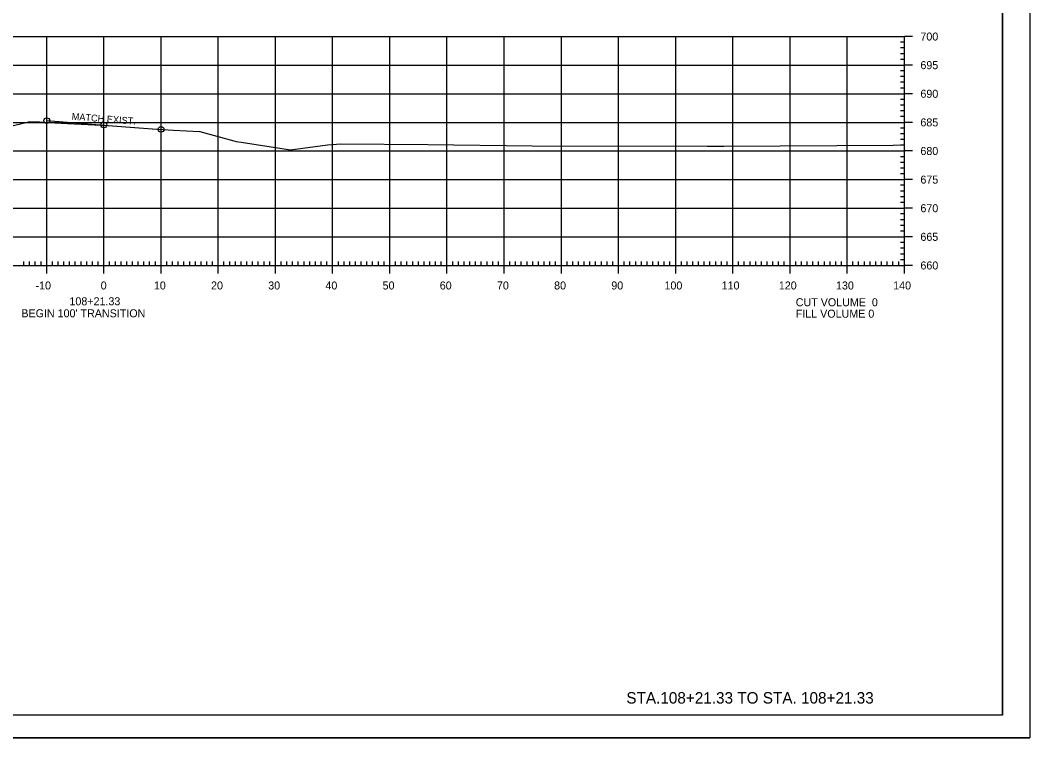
# Model space of a CAD drawing. Extents: x 1360146 to 1361431, y 631444 to 632352.
# Drawn here: x 1360303.1 to 1360479.7, y 631444.2 to 631569.6 of the extents above; entities that cross this region are included whole.
import ezdxf

# ---------------------------------------------------------------- set-up
doc = ezdxf.new("R2010")
doc.units = 0
for name, color, linetype in [('R_Axis', 7, 'Continuous'), ('R_Axis Annot', 7, 'Continuous'), ('R_Border', 7, 'Continuous'), ('R_Draft', 7, 'Continuous'), ('R_Exist Surface', 7, 'Continuous'), ('R_Fin Surface', 7, 'Continuous'), ('R_Fin Surface Annot', 7, 'Continuous'), ('R_Grid', 7, 'Continuous'), ('R_No Plot', 7, 'Continuous')]:
    doc.layers.add(name, color=color, linetype=linetype)

msp = doc.modelspace()

# ---------------------------------------------------------------- linework, layer by layer
at = {"layer": 'R_Axis'}
for p, q in [((1360457.77, 631526.7), (1360457.77, 631566.7)), ((1360459.17, 631566.7), (1360457.77, 631566.7)), ((1360457.77, 631565.7), (1360457.07, 631565.7)), ((1360457.77, 631564.7), (1360457.07, 631564.7)), ((1360457.77, 631563.7), (1360457.07, 631563.7)), ((1360457.77, 631562.7), (1360457.07, 631562.7)), ((1360459.17, 631561.7), (1360457.77, 631561.7)), ((1360457.77, 631560.7), (1360457.07, 631560.7)), ((1360457.77, 631559.7), (1360457.07, 631559.7)), ((1360457.77, 631558.7), (1360457.07, 631558.7)), ((1360457.77, 631557.7), (1360457.07, 631557.7)), ((1360459.17, 631556.7), (1360457.77, 631556.7)), ((1360457.77, 631555.7), (1360457.07, 631555.7)), ((1360457.77, 631554.7), (1360457.07, 631554.7)), ((1360457.77, 631553.7), (1360457.07, 631553.7)), ((1360457.77, 631552.7), (1360457.07, 631552.7)), ((1360459.17, 631551.7), (1360457.77, 631551.7)), ((1360457.77, 631550.7), (1360457.07, 631550.7)), ((1360457.77, 631549.7), (1360457.07, 631549.7)), ((1360457.77, 631548.7), (1360457.07, 631548.7)), ((1360457.77, 631547.7), (1360457.07, 631547.7)), ((1360457.77, 631545.7), (1360457.07, 631545.7)), ((1360459.17, 631546.7), (1360457.77, 631546.7)), ((1360457.77, 631544.7), (1360457.07, 631544.7)), ((1360457.77, 631543.7), (1360457.07, 631543.7)), ((1360457.77, 631542.7), (1360457.07, 631542.7)), ((1360457.77, 631540.7), (1360457.07, 631540.7)), ((1360459.17, 631541.7), (1360457.77, 631541.7)), ((1360457.77, 631539.7), (1360457.07, 631539.7)), ((1360457.77, 631538.7), (1360457.07, 631538.7)), ((1360457.77, 631537.7), (1360457.07, 631537.7)), ((1360459.17, 631536.7), (1360457.77, 631536.7)), ((1360457.77, 631535.7), (1360457.07, 631535.7)), ((1360457.77, 631534.7), (1360457.07, 631534.7)), ((1360457.77, 631533.7), (1360457.07, 631533.7)), ((1360457.77, 631532.7), (1360457.07, 631532.7)), ((1360459.17, 631531.7), (1360457.77, 631531.7)), ((1360457.77, 631530.7), (1360457.07, 631530.7)), ((1360457.77, 631529.7), (1360457.07, 631529.7)), ((1360457.77, 631528.7), (1360457.07, 631528.7)), ((1360177.77, 631526.7), (1360457.77, 631526.7)), ((1360303.77, 631526.7), (1360303.77, 631527.4)), ((1360304.77, 631526.7), (1360304.77, 631527.4)), ((1360305.77, 631526.7), (1360305.77, 631527.4)), ((1360306.77, 631526.7), (1360306.77, 631527.4)), ((1360307.77, 631525.3), (1360307.77, 631526.7)), ((1360308.77, 631526.7), (1360308.77, 631527.4)), ((1360309.77, 631526.7), (1360309.77, 631527.4)), ((1360310.77, 631526.7), (1360310.77, 631527.4)), ((1360311.77, 631526.7), (1360311.77, 631527.4)), ((1360312.77, 631526.7), (1360312.77, 631527.4)), ((1360313.77, 631526.7), (1360313.77, 631527.4)), ((1360314.77, 631526.7), (1360314.77, 631527.4)), ((1360315.77, 631526.7), (1360315.77, 631527.4)), ((1360316.77, 631526.7), (1360316.77, 631527.4)), ((1360317.77, 631525.3), (1360317.77, 631526.7)), ((1360318.77, 631526.7), (1360318.77, 631527.4)), ((1360319.77, 631526.7), (1360319.77, 631527.4)), ((1360320.77, 631526.7), (1360320.77, 631527.4)), ((1360321.77, 631526.7), (1360321.77, 631527.4)), ((1360322.77, 631526.7), (1360322.77, 631527.4)), ((1360323.77, 631526.7), (1360323.77, 631527.4)), ((1360324.77, 631526.7), (1360324.77, 631527.4)), ((1360325.77, 631526.7), (1360325.77, 631527.4)), ((1360326.77, 631526.7), (1360326.77, 631527.4)), ((1360327.77, 631525.3), (1360327.77, 631526.7)), ((1360328.77, 631526.7), (1360328.77, 631527.4)), ((1360329.77, 631526.7), (1360329.77, 631527.4)), ((1360330.77, 631526.7), (1360330.77, 631527.4)), ((1360331.77, 631526.7), (1360331.77, 631527.4)), ((1360332.77, 631526.7), (1360332.77, 631527.4)), ((1360333.77, 631526.7), (1360333.77, 631527.4)), ((1360334.77, 631526.7), (1360334.77, 631527.4)), ((1360335.77, 631526.7), (1360335.77, 631527.4)), ((1360336.77, 631526.7), (1360336.77, 631527.4)), ((1360337.77, 631525.3), (1360337.77, 631526.7)), ((1360338.77, 631526.7), (1360338.77, 631527.4)), ((1360339.77, 631526.7), (1360339.77, 631527.4)), ((1360340.77, 631526.7), (1360340.77, 631527.4)), ((1360341.77, 631526.7), (1360341.77, 631527.4)), ((1360342.77, 631526.7), (1360342.77, 631527.4)), ((1360343.77, 631526.7), (1360343.77, 631527.4)), ((1360344.77, 631526.7), (1360344.77, 631527.4)), ((1360345.77, 631526.7), (1360345.77, 631527.4)), ((1360346.77, 631526.7), (1360346.77, 631527.4)), ((1360347.77, 631525.3), (1360347.77, 631526.7)), ((1360348.77, 631526.7), (1360348.77, 631527.4)), ((1360349.77, 631526.7), (1360349.77, 631527.4)), ((1360350.77, 631526.7), (1360350.77, 631527.4)), ((1360351.77, 631526.7), (1360351.77, 631527.4)), ((1360352.77, 631526.7), (1360352.77, 631527.4)), ((1360353.77, 631526.7), (1360353.77, 631527.4)), ((1360354.77, 631526.7), (1360354.77, 631527.4)), ((1360355.77, 631526.7), (1360355.77, 631527.4)), ((1360356.77, 631526.7), (1360356.77, 631527.4)), ((1360357.77, 631525.3), (1360357.77, 631526.7)), ((1360358.77, 631526.7), (1360358.77, 631527.4)), ((1360359.77, 631526.7), (1360359.77, 631527.4)), ((1360360.77, 631526.7), (1360360.77, 631527.4)), ((1360361.77, 631526.7), (1360361.77, 631527.4)), ((1360362.77, 631526.7), (1360362.77, 631527.4)), ((1360363.77, 631526.7), (1360363.77, 631527.4)), ((1360364.77, 631526.7), (1360364.77, 631527.4)), ((1360365.77, 631526.7), (1360365.77, 631527.4)), ((1360366.77, 631526.7), (1360366.77, 631527.4)), ((1360367.77, 631525.3), (1360367.77, 631526.7)), ((1360368.77, 631526.7), (1360368.77, 631527.4)), ((1360369.77, 631526.7), (1360369.77, 631527.4)), ((1360370.77, 631526.7), (1360370.77, 631527.4)), ((1360371.77, 631526.7), (1360371.77, 631527.4)), ((1360372.77, 631526.7), (1360372.77, 631527.4)), ((1360373.77, 631526.7), (1360373.77, 631527.4)), ((1360374.77, 631526.7), (1360374.77, 631527.4)), ((1360375.77, 631526.7), (1360375.77, 631527.4)), ((1360376.77, 631526.7), (1360376.77, 631527.4)), ((1360377.77, 631525.3), (1360377.77, 631526.7)), ((1360378.77, 631526.7), (1360378.77, 631527.4)), ((1360379.77, 631526.7), (1360379.77, 631527.4)), ((1360380.77, 631526.7), (1360380.77, 631527.4)), ((1360381.77, 631526.7), (1360381.77, 631527.4)), ((1360382.77, 631526.7), (1360382.77, 631527.4)), ((1360383.77, 631526.7), (1360383.77, 631527.4)), ((1360384.77, 631526.7), (1360384.77, 631527.4)), ((1360385.77, 631526.7), (1360385.77, 631527.4)), ((1360386.77, 631526.7), (1360386.77, 631527.4)), ((1360387.77, 631525.3), (1360387.77, 631526.7)), ((1360388.77, 631526.7), (1360388.77, 631527.4)), ((1360389.77, 631526.7), (1360389.77, 631527.4)), ((1360390.77, 631526.7), (1360390.77, 631527.4)), ((1360391.77, 631526.7), (1360391.77, 631527.4)), ((1360392.77, 631526.7), (1360392.77, 631527.4)), ((1360393.77, 631526.7), (1360393.77, 631527.4)), ((1360394.77, 631526.7), (1360394.77, 631527.4)), ((1360395.77, 631526.7), (1360395.77, 631527.4)), ((1360396.77, 631526.7), (1360396.77, 631527.4)), ((1360397.77, 631525.3), (1360397.77, 631526.7)), ((1360398.77, 631526.7), (1360398.77, 631527.4)), ((1360399.77, 631526.7), (1360399.77, 631527.4)), ((1360400.77, 631526.7), (1360400.77, 631527.4)), ((1360401.77, 631526.7), (1360401.77, 631527.4)), ((1360402.77, 631526.7), (1360402.77, 631527.4)), ((1360403.77, 631526.7), (1360403.77, 631527.4)), ((1360404.77, 631526.7), (1360404.77, 631527.4)), ((1360405.77, 631526.7), (1360405.77, 631527.4)), ((1360406.77, 631526.7), (1360406.77, 631527.4)), ((1360407.77, 631525.3), (1360407.77, 631526.7)), ((1360408.77, 631526.7), (1360408.77, 631527.4)), ((1360409.77, 631526.7), (1360409.77, 631527.4)), ((1360410.77, 631526.7), (1360410.77, 631527.4)), ((1360411.77, 631526.7), (1360411.77, 631527.4)), ((1360412.77, 631526.7), (1360412.77, 631527.4)), ((1360413.77, 631526.7), (1360413.77, 631527.4)), ((1360414.77, 631526.7), (1360414.77, 631527.4)), ((1360415.77, 631526.7), (1360415.77, 631527.4)), ((1360416.77, 631526.7), (1360416.77, 631527.4)), ((1360417.77, 631525.3), (1360417.77, 631526.7)), ((1360418.77, 631526.7), (1360418.77, 631527.4)), ((1360419.77, 631526.7), (1360419.77, 631527.4)), ((1360420.77, 631526.7), (1360420.77, 631527.4)), ((1360421.77, 631526.7), (1360421.77, 631527.4)), ((1360422.77, 631526.7), (1360422.77, 631527.4)), ((1360423.77, 631526.7), (1360423.77, 631527.4)), ((1360424.77, 631526.7), (1360424.77, 631527.4)), ((1360425.77, 631526.7), (1360425.77, 631527.4)), ((1360426.77, 631526.7), (1360426.77, 631527.4)), ((1360427.77, 631525.3), (1360427.77, 631526.7)), ((1360428.77, 631526.7), (1360428.77, 631527.4)), ((1360429.77, 631526.7), (1360429.77, 631527.4)), ((1360430.77, 631526.7), (1360430.77, 631527.4)), ((1360431.77, 631526.7), (1360431.77, 631527.4)), ((1360432.77, 631526.7), (1360432.77, 631527.4)), ((1360433.77, 631526.7), (1360433.77, 631527.4)), ((1360434.77, 631526.7), (1360434.77, 631527.4)), ((1360435.77, 631526.7), (1360435.77, 631527.4)), ((1360436.77, 631526.7), (1360436.77, 631527.4)), ((1360437.77, 631525.3), (1360437.77, 631526.7)), ((1360438.77, 631526.7), (1360438.77, 631527.4)), ((1360439.77, 631526.7), (1360439.77, 631527.4)), ((1360440.77, 631526.7), (1360440.77, 631527.4)), ((1360441.77, 631526.7), (1360441.77, 631527.4)), ((1360442.77, 631526.7), (1360442.77, 631527.4)), ((1360443.77, 631526.7), (1360443.77, 631527.4)), ((1360444.77, 631526.7), (1360444.77, 631527.4)), ((1360445.77, 631526.7), (1360445.77, 631527.4)), ((1360446.77, 631526.7), (1360446.77, 631527.4)), ((1360447.77, 631525.3), (1360447.77, 631526.7)), ((1360448.77, 631526.7), (1360448.77, 631527.4)), ((1360449.77, 631526.7), (1360449.77, 631527.4)), ((1360450.77, 631526.7), (1360450.77, 631527.4)), ((1360451.77, 631526.7), (1360451.77, 631527.4)), ((1360452.77, 631526.7), (1360452.77, 631527.4)), ((1360453.77, 631526.7), (1360453.77, 631527.4)), ((1360454.77, 631526.7), (1360454.77, 631527.4)), ((1360455.77, 631526.7), (1360455.77, 631527.4)), ((1360456.77, 631526.7), (1360456.77, 631527.4)), ((1360457.77, 631527.7), (1360457.07, 631527.7)), ((1360457.77, 631525.3), (1360457.77, 631526.7)), ((1360459.17, 631526.7), (1360457.77, 631526.7))]:
    msp.add_line(p, q, dxfattribs=at)
at = {"layer": 'R_Border'}
for q in [(1360474.95, 631653.6), (1360158.77, 631448.14)]:
    msp.add_line((1360474.95, 631448.14), q, dxfattribs=at)
at = {"layer": 'R_Exist Surface'}
msp.add_lwpolyline([(1360296.5, 631549.82), (1360304.82, 631551.87), (1360306.49, 631551.8), (1360308.06, 631551.7), (1360311.39, 631551.53), (1360318.51, 631551.14), (1360326.2, 631550.6), (1360329.94, 631550.32), (1360334.5, 631550.1), (1360334.54, 631550.09), (1360340.5, 631548.46), (1360340.89, 631548.37), (1360341.78, 631548.24), (1360350.38, 631546.92), (1360356.88, 631547.76), (1360359.2, 631547.98), (1360374.4, 631547.82), (1360392.65, 631547.58), (1360423.26, 631547.55), (1360425.06, 631547.55), (1360426.2, 631547.55), (1360455.81, 631547.73), (1360457.77, 631547.77)], dxfattribs=at)
at = {"layer": 'R_Fin Surface'}
msp.add_lwpolyline([(1360307.77, 631552), (1360307.77, 631552), (1360307.77, 631552), (1360317.76, 631551.24), (1360317.77, 631551.24), (1360327.76, 631550.48), (1360327.77, 631550.48), (1360327.77, 631550.48), (1360327.77, 631550.48)], dxfattribs=at)
at = {"layer": 'R_Grid'}
for p, q in [((1360177.77, 631566.7), (1360457.77, 631566.7)), ((1360307.77, 631526.7), (1360307.77, 631566.7)), ((1360317.77, 631526.7), (1360317.77, 631566.7)), ((1360327.77, 631526.7), (1360327.77, 631566.7)), ((1360337.77, 631526.7), (1360337.77, 631566.7)), ((1360347.77, 631526.7), (1360347.77, 631566.7)), ((1360357.77, 631526.7), (1360357.77, 631566.7)), ((1360367.77, 631526.7), (1360367.77, 631566.7)), ((1360377.77, 631526.7), (1360377.77, 631566.7)), ((1360387.77, 631526.7), (1360387.77, 631566.7)), ((1360397.77, 631526.7), (1360397.77, 631566.7)), ((1360407.77, 631526.7), (1360407.77, 631566.7)), ((1360417.77, 631526.7), (1360417.77, 631566.7)), ((1360427.77, 631526.7), (1360427.77, 631566.7)), ((1360437.77, 631526.7), (1360437.77, 631566.7)), ((1360447.77, 631526.7), (1360447.77, 631566.7)), ((1360457.77, 631526.7), (1360457.77, 631566.7)), ((1360177.77, 631561.7), (1360457.77, 631561.7)), ((1360177.77, 631556.7), (1360457.77, 631556.7)), ((1360177.77, 631551.7), (1360457.77, 631551.7)), ((1360177.77, 631546.7), (1360457.77, 631546.7)), ((1360177.77, 631541.7), (1360457.77, 631541.7)), ((1360177.77, 631536.7), (1360457.77, 631536.7)), ((1360177.77, 631531.7), (1360457.77, 631531.7)), ((1360177.77, 631526.7), (1360457.77, 631526.7))]:
    msp.add_line(p, q, dxfattribs=at)
at = {"layer": 'R_No Plot'}
msp.add_line((1360146.37, 631444.17), (1360479.7, 631444.17), dxfattribs=at)
for points in [[(1360146.36, 631657.5), (1360479.7, 631657.5), (1360479.7, 631444.16), (1360146.36, 631444.16)], [(1360392.69, 631653.6), (1360392.69, 631643.72), (1360428.42, 631643.72), (1360428.42, 631640.8), (1360451.62, 631640.8), (1360451.62, 631616.47), (1360474.95, 631616.47), (1360474.95, 631448.14), (1360158.77, 631448.14), (1360158.77, 631653.6)]]:
    msp.add_lwpolyline(points, close=True, dxfattribs=at)
for centre in [(1360307.77, 631552), (1360317.77, 631551.24), (1360327.77, 631550.48)]:
    msp.add_circle(centre, 0.5, dxfattribs=at)

# ---------------------------------------------------------------- texts
at = {"layer": 'R_Axis Annot'}
for s, p in [('700', (1360460.57, 631566)), ('695', (1360460.57, 631561)), ('690', (1360460.57, 631556)), ('685', (1360460.57, 631551)), ('680', (1360460.57, 631546)), ('675', (1360460.57, 631541)), ('670', (1360460.57, 631536)), ('665', (1360460.57, 631531)), ('660', (1360460.57, 631526)), ('-10', (1360305.81, 631522.5)), ('0', (1360317.21, 631522.5)), ('10', (1360326.51, 631522.5)), ('20', (1360336.51, 631522.5)), ('30', (1360346.51, 631522.5)), ('40', (1360356.51, 631522.5)), ('50', (1360366.51, 631522.5)), ('60', (1360376.51, 631522.5)), ('70', (1360386.51, 631522.5)), ('80', (1360396.51, 631522.5)), ('90', (1360406.51, 631522.5)), ('100', (1360415.81, 631522.5)), ('110', (1360425.81, 631522.5)), ('120', (1360435.81, 631522.5)), ('130', (1360445.81, 631522.5)), ('140', (1360455.81, 631522.5)), ('108+21.33', (1360311.74, 631519.74)), ('CUT VOLUME  0', (1360438.77, 631519.57)), ("BEGIN 100' TRANSITION", (1360303.33, 631517.64)), ('FILL VOLUME 0', (1360438.77, 631517.57))]:
    msp.add_text(s, height=1.4, dxfattribs=at).set_placement(p)
at = {"layer": 'R_Draft'}
msp.add_text('STA.108+21.33 TO STA. 108+21.33', height=2, dxfattribs=at).set_placement((1360409.14, 631450.14))
at = {"layer": 'R_Fin Surface Annot'}
msp.add_text('MATCH EXIST.', height=1.2, rotation=355.6497, dxfattribs=at).set_placement((1360312.1, 631552.16))

doc.saveas('drawing.dxf')
